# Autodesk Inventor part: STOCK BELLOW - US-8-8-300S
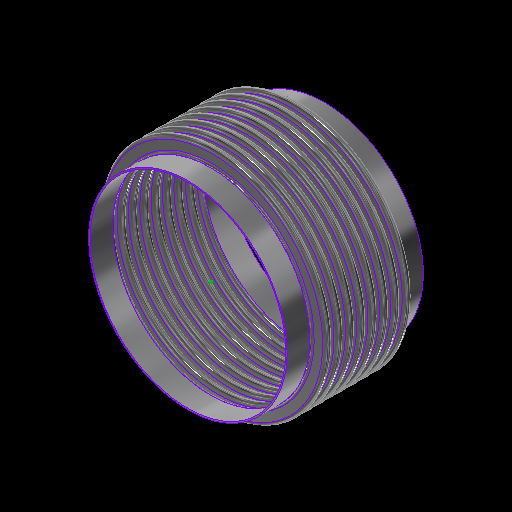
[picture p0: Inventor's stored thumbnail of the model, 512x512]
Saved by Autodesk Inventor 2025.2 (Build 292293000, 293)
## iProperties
Category: 22 GA (0.030 THICK)
RuleStatus: InUse
Created: 2024-01
Part Number: STOCK BELLOW - US-8-8-300S
Project: =STOCK BELLOWS: <Stock Number><SFILL>
Material: ASTM A240-304
Description: =STOCK BELLOWS: <Stock Number>, <SID_> I.D., <SOD_> O.D., <SPLY_> PLY, <Category>, <SNET_CONS> CONS.<PITCH_><STANGENT_> TANGENT<SFILL>
Document SubType Name: Sheet Metal
Designer: GS
Stock Number: U.S-8-8-300S
Surface Area: 5419.46 cm^2
Volume: 408.134 cm^3
Sheet Metal Rule: Default
Appearance: STAINLESS STEEL
Mass: 3288.45 g
Density: 8.05729 g/cm^3
THK: 0.036
ID: 3.500
OD: 4.250
CONS_: 2
PITCH: 0.500
TANGENT: 0.500
BELLOWS_UPSET: 0.000
d79: 1.000
d82: 1.000
d83: 26.000
d84: 24.000
d174: 8
d214: 8
STHK_: 0.030
SID_: 8.625
SOD_: 10.000
SPITCH_: 0.500
STANGENT__: 1.000
SBELLOWS_UPSET_: 0.000
SDIFF_TAN: 1.000
d252: 2
d275: 2
d287: 0.050
d289: 0.500
d290: 0.000
SOD_NECK: 8 3/4
PLY: 1
PSET: 4.178
PBAR: 1.035
COUNTER: 1.500
NET_TUBE: 3.071
CONS: 2
S_CONS: 0
NET_CONS: 2
ID_M: 88.90 mm
OD_M: 107.95 mm
THK_M: 0.91 mm
ID_U: 3.500 in
OD_U: 4.250 in
THK_U: 0.036 in
TANGENT2: 0.500
TAN_TO_TAN: 1.000 in
d80: 2.571
d81: 10
SID: 2.375
SCONS_: 8
SPITCH: 0.250
STANGENT_: 1.000
SBELLOWS_UPSET: 0.000
SNET_CONS: 8
SS_CONS: 0
SCONS: 8
d190: 8
d191: 1
d192: 1
d193: 8
d194: 0
SIZE: 8.00
PRESSURE: 300
d230: 8
STANGENT: 4.000
SPLY_: 2
d233: 8
d234: 0
d263: 2
d265: 1
d268: 2
d269: 0
d286: 2
d288: 1
d291: 2
d292: 0
SREROLL: 0.750
BLETP: 0.000 ul
PRES_Copy: 85
MATTABLE: 20 GA (0.036 THICK)
PART_NUMBER: U.S-8-8-300S
PITCH_: =, <SPITCH_> PITCH,
CFILL: .
SFILL: .
MESH: ,
COMP: 0.82
EXT: 0.41
LAT: 0.11
ANG: 573
ASR: 3697
LSR: 30059
ANSR: 700
PRES: 300
COMPM: 8.2
EXTM: 4.1
LATM: 1.10
ASRM: 647.456
PRESM: 20.684
LSRM: 5264.233
ANSRM: 122.591
TEMPMIN: 20
TEMPMAX: 800
TEMPMINM: -7
TEMPMAXM: 427
WEIGHTM: 3.288
WEIGHT: 7.250
Author: GS
Keywords: 20 GA (0.036 THICK)
Comments: =STOCK BELLOW - <STOCK NUMBER>
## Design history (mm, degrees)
sketch "Sketch2"
  geometry: L1 (0, -177.245)-(0, 562.856) reference; L2 (45.364, 0)-(44.45, 0); L3 (48.082, -2.718)-(50.343, -2.718); L4 (48.082, -3.632)-(50.343, -3.632); L5 (50.343, -9.982)-(48.082, -9.982); L6 (50.343, -9.068)-(48.082, -9.068); L7 (45.364, -12.7)-(44.45, -12.7); L8 (48.082, 0)-(48.082, -12.7); L9 (50.343, -6.35)-(53.975, -6.35); L10 (44.45, 0)-(44.45, -12.7); L11 (20.376, 102.841)-(20.376, 101.926); L12 (58.262, 457.127)-(58.262, 349.177); L13 (58.262, 444.427)-(58.262, 336.477); L14 (93.133, -58.817)-(93.133, -71.517); L15 (118.746, -66.401)-(118.746, -66.401); L16 (50.343, -9.068)-(50.343, -9.982); L17 (48.082, -9.068)-(48.082, -9.982); L18 (48.082, -9.525)-(50.343, -9.525); L19 (53.975, 0)-(53.975, -12.7); L20 (-50.343, -9.068)-(-50.343, -9.982); L21 (-50.343, -2.718)-(-48.082, -2.718); L22 (-50.343, -3.632)-(-48.082, -3.632); L23 (-48.082, -9.068)-(-50.343, -9.068); L24 (-50.343, -9.525)-(-48.082, -9.525); L25 (-48.082, -9.982)-(-50.343, -9.982); L26 (-48.082, -9.068)-(-48.082, -9.982); L27 (-44.45, 0.653)-(-44.45, -12.047); L28 (-48.082, -6.35)-(-44.45, -6.35); L29 (-50.343, 0.653)-(-50.343, -12.7); L30 (-53.061, 0)-(-53.975, 0); L31 (-53.975, 0)-(-53.975, -12.7); L32 (-53.061, -12.7)-(-53.975, -12.7); A1 r 2.718 centre (48.082, 0) between (45.364, 0) and (48.082, -2.718); A2 r 3.632 centre (48.082, 0) between (44.45, 0) and (48.082, -3.632); A3 r 3.632 centre (50.343, -6.35) between (50.343, -9.982) and (50.343, -2.718); A4 r 2.718 centre (50.343, -6.35) between (50.343, -9.068) and (50.343, -3.632); A5 r 2.718 centre (48.082, -12.7) between (48.082, -9.982) and (45.364, -12.7); A6 r 3.632 centre (48.082, -12.7) between (48.082, -9.068) and (44.45, -12.7); A7 r 3.175 centre (50.343, -6.35) between (50.343, -9.525) and (53.518, -6.35); A8 r 3.175 centre (48.082, -12.7) between (48.082, -9.525) and (44.907, -12.7); A9 r 2.718 centre (-50.343, -12.7) between (-50.343, -9.982) and (-53.061, -12.7); A10 r 2.718 centre (-48.082, -6.35) between (-48.082, -9.068) and (-48.082, -3.632); A11 r 3.175 centre (-48.082, -6.35) between (-48.082, -9.525) and (-44.907, -6.35); A12 r 3.632 centre (-48.082, -6.35) between (-48.082, -9.982) and (-48.082, -2.718); A13 r 3.175 centre (-50.343, -12.7) between (-50.343, -9.525) and (-53.518, -12.7); A14 r 3.632 centre (-50.343, -12.7) between (-50.343, -9.068) and (-53.975, -12.7); A15 r 2.718 centre (-50.343, 0) between (-53.061, 0) and (-50.343, -2.718); A16 r 3.632 centre (-50.343, 0) between (-53.975, 0) and (-50.343, -3.632); 10 further points
  constraints: 62 end point, 38 point on circle, 20 tangent, 16 centre point, 12 parallel, 9 midpoint, 7 vertical, 6 coincident, 6 concentric, 6 point on line, 4 equal radius, 4 perpendicular, 3 horizontal, 1 collinear, 1 horizontal alignment, 10 other
  dimensions: "THK" = 0.9144 distance of L11.start L11.end; "ID" = 88.9 distance of L11.end point (20.376, 13.026); "OD" = 107.95 distance of L12.start L12.end; "PITCH" = 12.7 distance of L12.start L13.start; "TANGENT" = 12.7 distance of L14.start L14.end; "BELLOWS_UPSET" = 0 distance of L15.start L15.end; "d43" = 88.9 diameter of L10 L1 (= ID); "d44" = 107.95 diameter of L9.end L1 (= OD); "d45" = 0.9144 distance between parallel lines of L5 L6 (computed from THK, PLY); "d46" = 3.6322 radius of A3 (computed from PITCH, THK, PLY); "UPSET_PITCH" = 12.7 distance of L2.end L7.end (derived); "SIDEWALL_ANGLE" = 360 deg dimension on L3 L9 (derived); "CON_GAP" = 5.4356 distance of point (48.082, -9.068) point (48.082, -3.632) (derived); "TAN1" = 4.98728 dimension on A8 (derived); "TAN2" = 4.98728 dimension on A7 (derived); "LEG1" = 2.2606 distance of L18.start L18.end (derived); "d278" = 0.9144 distance between parallel lines of L25 L23 (derived); "d279" = 3.6322 radius of A12 (derived); "d280" = 12.7 distance of L30.end L31.end (derived); "d281" = 360 deg dimension on L21 L28 (derived); "d282" = 5.4356 distance of point (-50.343, -9.068) point (-50.343, -3.632) (derived); "d283" = 4.98728 dimension on A13 (derived); "d284" = 4.98728 dimension on A11 (derived); "d285" = 2.2606 distance of L24.start L24.end (derived); "d293" = 88.9 diameter of L27 L1 (derived); "d294" = 107.95 diameter of L31 L1 (derived)
  node "Sketch Rectangular Pattern1" dims "d31" = 25.4, "ID" = 88.9
  node "Sketch Rectangular Pattern2" dims "d39" = 25.4, "PITCH" = 12.7
revolve "CONS" stored, may be unused: angle "d48" = 90 deg
node "BELLOW MIDPLANE"
pattern_linear "Rectangular Pattern2" dims "d52" = 12.7 (= UPSET_PITCH)
sketch "Sketch5"
  geometry: C1 r 45.364 at (0, 0) reference; C2 r 44.45 at (0, 0) reference
extrude "TANGENT" new body sketch "Sketch5" distance "d53" = 12.7 (= TANGENT); taper "d54" = 0 deg
revolve "SAMETAN" stored, may be unused: angle "d65" = 90 deg
revolve "DIFFTAN" stored, may be unused: angle "d70" = 90 deg
sketch "Sketch9"
  geometry: L1 (53.319, 0)-(-53.319, 0) reference; L2 (0, -17.78)-(0, 17.78) reference; L3 (38.085, 0)-(-38.085, 0); L4 (38.085, -11.906)-(38.085, 11.906); L5 (25.385, -11.906)-(25.385, 11.906); L6 (13.15, 11.906)-(13.15, -11.906); L7 (-25.385, -11.906)-(-25.385, 11.906); L8 (-38.085, -11.906)-(-38.085, 11.906); L9 (37.291, -11.906)-(37.291, 11.906); L10 (38.085, -11.906)-(37.291, -11.906); L11 (38.085, 11.906)-(37.291, 11.906); L12 (13.546, 11.906)-(12.753, 11.906); L13 (12.753, 11.906)-(12.753, -11.906); L14 (12.753, -11.906)-(13.546, -11.906); L15 (13.546, -11.906)-(13.546, 11.906); L16 (-13.546, 11.906)-(-13.546, -11.906); L17 (-13.15, 11.906)-(-13.15, -11.906); L18 (-13.546, -11.906)-(-12.753, -11.906); L19 (-12.753, -11.906)-(-12.753, 11.906); L20 (-12.753, 11.906)-(-13.546, 11.906); L21 (-38.085, -11.906)-(-37.291, -11.906); L22 (-37.291, -11.906)-(-37.291, 11.906); L23 (-37.291, 11.906)-(-38.085, 11.906); L24 (-38.085, 11.906)-(-38.085, -11.906); L25 (38.085, -0.397)-(-38.085, -0.397); L26 (-38.085, -0.397)-(-38.085, 0.397); L27 (-38.085, 0.397)-(38.085, 0.397); L28 (38.085, 0.397)-(38.085, -0.397); L29 (-38.085, 11.906)-(38.085, 11.906); L30 (38.085, 11.906)-(38.085, 12.7); L31 (38.085, 12.7)-(-38.085, 12.7); L32 (-38.085, 12.7)-(-38.085, 11.906); L33 (38.085, -11.906)-(-38.085, -11.906); L34 (-38.085, -11.906)-(-38.085, -12.7); L35 (-38.085, -12.7)-(38.085, -12.7); L36 (38.085, -12.7)-(38.085, -11.906); 30 further points
  constraints: 68 end point, 13 midpoint, 13 parallel, 8 horizontal, 7 perpendicular, 6 equal length, 3 point on line, 2 vertical, 14 other
  dimensions: "d115" = 23.8125 distance of L4.start L4.end (derived); "d116" = 12.7 distance between parallel lines of L4 L5 (derived); "d117" = 12.23516 distance between parallel lines of L5 L6 (derived); "d125" = 38.53427 distance between parallel lines of L7 L6 (derived); "d127" = 12.7 distance between parallel lines of L8 L7 (derived); "d128" = 24.93516 distance between parallel lines of L6 L4 (derived); "d130" = 76.16943 distance between parallel lines of L8 L4 (derived); "RULER_THK" = 0.79375 distance between parallel lines of L4 L9; "d135" = 0.79375 distance of L13.end L14.end (derived); "d138" = 26.29911 distance of L13.end L16.end (derived); "d143" = 0.79375 distance of L22.end L8.end (derived); "d144" = 0.79375 distance between parallel lines of L27 L25 (derived)
extrude "RULER" join sketch "Sketch9" distance "d149" = 0.79375 (derived); taper "d150" = 0 deg
extrude "BARS" join sketch "Sketch9" distance "d151" = 0.79375 (derived); taper "d152" = 0 deg
pattern_linear "Rectangular Pattern4" dims "d155" = 26.29911 (derived)
sketch "Sketch13"
  geometry: L1 (93.149, -52.467)-(93.149, -77.867); L2 (111.061, 0)-(109.537, 0); L3 (111.061, -12.7)-(109.537, -12.7); L4 (123.063, -10.287)-(113.475, -10.287); L5 (123.063, -8.763)-(113.475, -8.763); L6 (123.063, -6.35)-(127, -6.35); L7 (113.475, -2.413)-(123.063, -2.413); L8 (113.475, 0)-(113.475, -12.7); L9 (109.537, 0)-(109.537, -12.7); L10 (58.254, -242.431)-(58.254, -496.431); L11 (58.254, -255.131)-(58.254, -509.131); L12 (58.254, -280.531)-(58.254, -534.531); L13 (58.254, -293.231)-(58.254, -547.231); L14 (58.254, -305.931)-(58.254, -559.931); L15 (58.254, -318.631)-(58.254, -572.631); L16 (58.254, -331.331)-(58.254, -585.331); L17 (58.254, -267.831)-(58.254, -521.831); L18 (20.376, 102.688)-(20.376, 101.926); L19 (113.475, -3.937)-(123.063, -3.937); L20 (0, -722.935)-(0, 240.292) reference; L21 (-25.4, 0)-(152.4, 0) reference; A1 r 2.413 centre (113.475, 0) between (111.061, 0) and (113.475, -2.413); A2 r 2.413 centre (113.475, -12.7) between (113.475, -10.287) and (111.061, -12.7); A3 r 3.937 centre (113.475, -12.7) between (113.475, -8.763) and (109.537, -12.7); A4 r 2.413 centre (123.063, -6.35) between (123.063, -8.763) and (123.063, -3.937); A5 r 3.937 centre (123.063, -6.35) between (123.063, -10.287) and (123.063, -2.413); A6 r 3.937 centre (113.475, 0) between (109.537, 0) and (113.475, -3.937); 6 further points; 1 other entity
  constraints: 38 end point, 15 point on circle, 9 tangent, 6 centre point, 6 parallel, 5 vertical alignment, 4 point on line, 4 vertical, 3 coincident, 3 concentric, 2 collinear, 2 equal radius, 1 horizontal, 1 perpendicular, 23 other
  dimensions: "SBELLOWS_UPSET_" = 0 distance of point (118.762, -66.401) point (118.762, -66.401); "STOTAL_THK_BELLOW__" = 1.524 distance between parallel lines of L4 L5 (derived); "d224" = 3.937 radius of A5 (derived); "d225" = 12.7 distance of L2.end L3.end (derived); "SSIDEWALL_ANGLE_" = 360 deg dimension on L7 L6 (derived); "SSCON_GAP_" = 4.826 distance of point (113.474, -8.763) point (113.475, -3.937) (derived); "d235" = 219.075 diameter of L9 L20 (derived); "d236" = 254 diameter of L6.end L20 (derived)
  node "Sketch Rectangular Pattern4" dims "d228" = 25.4
  node "Sketch Rectangular Pattern5" dims "d229" = 25.4
revolve "SBELLOW" stored, may be unused: angle "d197" = 90 deg
pattern_linear "Rectangular Pattern5" dims "d204" = 12.7 (derived)
revolve "STANGENT" stored, may be unused: angle "d240" = 90 deg
revolve "SSAMETAN" stored, may be unused: angle "d241" = 90 deg
revolve "SDIFFTAN" stored, may be unused: angle "d246" = 90 deg
revolve "INVCON" stored, may be unused: angle "d295" = 90 deg
pattern_linear "Rectangular Pattern6" dims "d298" = 12.7 (derived)
revolve "INVTANGENT" stored, may be unused: angle "d302" = 90 deg
revolve "INVSAMETAN" stored, may be unused: angle "d307" = 90 deg
revolve "INVDIFFTAN" stored, may be unused: angle "d312" = 90 deg
sketch "ID BELLOW MOUNT CALC"
  geometry: L1 (44.45, 0)-(38.1, 0); L2 (38.1, 0)-(38.1, 12.7); L3 (38.1, 12.7)-(44.45, 12.7); L4 (44.45, 12.7)-(44.45, 0); L5 (36.513, 12.7)-(35.598, 12.7); L6 (35.598, 12.7)-(35.598, 0); L7 (35.598, 0)-(36.513, 0); L8 (36.513, 0)-(36.513, 12.7); L9 (0, -2.54)-(0, 15.24) reference; L10 (-8.89, 0)-(53.34, 0) reference; 1 further point
  constraints: 16 end point, 5 parallel, 2 collinear, 2 horizontal, 2 perpendicular
  dimensions: "d314" = 12.7 distance of L5.end L6.end (derived); "d315" = 0.9144 distance of L5.start L5.end (derived); "IG" = 1.5875 distance between parallel lines of L2 L8; "PIPE_OD" = 88.9 diameter of L4 L9; "PIPE_WALL" = 6.35 distance of L2.end L3.end; "ID_MT_BELLOW" = 71.1962 diameter of L6 L9 (derived)
revolve "CFILL" stored, may be unused: angle "d320" = 90 deg
pattern_linear "Rectangular Pattern7" dims "d323" = 12.7 (derived)
revolve "SFILL" stored, may be unused: angle "d324" = 90 deg
pattern_linear "Rectangular Pattern8" dims "d327" = 12.7 (derived)
node "STOCK BELLOW MIDPLANE"
node "BELLOW"
sketch "Sketch6"
  geometry: L1 (-12.7, 45.364)-(0, 45.364); L2 (0, 45.364)-(0, 44.45); L3 (0, 44.45)-(-12.7, 44.45); L4 (-12.7, 44.45)-(-12.7, 45.364); L5 (10.16, 0)-(-60.96, 0) reference; L6 (-38.1, -89.422)-(-38.1, 153.44) reference; 1 further point
  constraints: 8 end point, 2 parallel, 1 horizontal, 1 perpendicular
  dimensions: "d61" = 12.7 distance of L2.end L3.end (derived); "d62" = 0.9144 distance of L1.end L2.end (derived); "d63" = 88.9 diameter of L3 L5 (derived); "d64" = 25.4 distance between parallel lines of L4 L6 (derived)
sketch "Sketch12"
  geometry: 1 further point
sketch "Sketch14"
  geometry: L1 (-25.4, 111.061)-(0, 111.061); L2 (0, 111.061)-(0, 109.537); L3 (0, 109.537)-(-25.4, 109.537); L4 (-25.4, 109.537)-(-25.4, 111.061); L5 (5.08, 0)-(-30.48, 0) reference; L6 (0, -22.212)-(0, 133.274) reference; 1 further point
  constraints: 8 end point, 2 parallel, 1 collinear, 1 horizontal, 1 perpendicular
  dimensions: "d237" = 1.524 distance of L3.end L1.start (derived); "d238" = 219.075 diameter of L3 L5 (derived); "d239" = 25.4 distance of L1.start L1.end (derived); "SOD_NECK" = 222.123 diameter of L1 L5 (derived)
sketch "Sketch15"
  geometry: L1 (-22.212, 0)-(133.274, 0) reference; L2 (109.538, -101.6)-(111.062, -101.6); L3 (111.062, -101.6)-(111.062, -127); L4 (111.062, -127)-(109.537, -127); L5 (109.537, -127)-(109.538, -101.6); L6 (0, -154.94)-(0, 40.64) reference; 1 further point
  constraints: 8 end point, 2 parallel, 1 horizontal, 1 perpendicular
  dimensions: "d205" = 25.4 distance of L4.end L2.start (derived); "d206" = 1.524 distance of L3.end L4.end (derived); "d207" = 219.075 diameter of L5 L6 (derived); "d208" = 101.6 distance between parallel lines of L1 L2 (derived)
node "TANGENT_"
node "SAME_TAN"
sketch "Sketch8"
  geometry: L1 (45.364, -25.4)-(44.45, -25.4); L2 (44.45, -25.4)-(44.45, -38.1); L3 (44.45, -38.1)-(45.364, -38.1); L4 (45.364, -38.1)-(45.364, -25.4); L5 (0, -48.26)-(0, 22.86) reference; L6 (-89.422, 0)-(153.44, 0) reference; 1 further point
  constraints: 8 end point, 2 parallel, 1 horizontal, 1 perpendicular
  dimensions: "d66" = 88.9 diameter of L2 L5 (derived); "TOTAL_THK_BELLOW" = 0.9144 distance of L2.end L3.end (derived); "d68" = 25.4 distance between parallel lines of L1 L6 (derived); "d69" = 12.7 distance of L1.end L2.end (derived)
node "DIFF_TAN"
node "Sketch Rectangular Pattern3" dims "d138" = 26.29911 (derived), "d141" = 25.4
node "SBELLOW_"
node "STANGENT_"
node "SSAME_TAN"
sketch "Sketch16"
  geometry: L1 (111.061, -101.6)-(109.538, -101.6); L2 (109.538, -101.6)-(109.538, -127); L3 (109.538, -127)-(111.062, -127); L4 (111.062, -127)-(111.061, -101.6); L5 (0, -154.94)-(0, 40.64) reference; L6 (-22.212, 0)-(133.274, 0) reference; 1 further point
  constraints: 8 end point, 2 parallel, 1 horizontal, 1 perpendicular
  dimensions: "SDIFF_TAN" = 25.4 distance of L3.end L1.start; "d243" = 1.524 distance of L2.end L3.end (derived); "d244" = 101.6 distance between parallel lines of L1 L6 (derived); "d245" = 219.075 diameter of L2 L5 (derived)
node "SDIFF_TAN"
body "Solid15"
sketch "Sketch17"
  geometry: L1 (53.975, 12.7)-(53.061, 12.7); L2 (53.061, 12.7)-(53.061, 0); L3 (53.061, 0)-(53.975, 0); L4 (53.975, 0)-(53.975, 12.7); L5 (0, -2.54)-(0, 15.24) reference; L6 (-10.795, 0)-(64.77, 0) reference; 2 further points
  constraints: 8 end point, 2 parallel, 1 horizontal, 1 midpoint, 1 perpendicular, 1 point on line
  dimensions: "INVTANGENT" = 12.7 distance of L3.end L1.start (derived); "d300" = 0.9144 distance of L1.start L1.end (derived); "d301" = 107.95 diameter of L4 L5 (derived)
body "Solid16"
sketch "Sketch18"
  geometry: L1 (53.975, -25.4)-(53.061, -25.4); L2 (53.061, -25.4)-(53.061, -38.1); L3 (53.061, -38.1)-(53.975, -38.1); L4 (53.975, -38.1)-(53.975, -25.4); L5 (-10.795, 0)-(64.77, 0) reference; L6 (0, -48.26)-(0, 22.86) reference; 1 further point
  constraints: 8 end point, 2 parallel, 1 horizontal, 1 perpendicular
  dimensions: "d303" = 25.4 distance between parallel lines of L1 L5 (derived); "d304" = 12.7 distance of L3.end L1.start (derived); "d305" = 0.9144 distance of L2.end L3.end (derived); "d306" = 107.95 diameter of L4 L6 (derived)
body "Solid17"
sketch "Sketch19"
  geometry: L1 (53.975, -25.4)-(53.061, -25.4); L2 (53.061, -25.4)-(53.061, -38.1); L3 (53.061, -38.1)-(53.975, -38.1); L4 (53.975, -38.1)-(53.975, -25.4); L5 (0, -48.26)-(0, 22.86) reference; L6 (-10.795, 0)-(64.77, 0) reference; 1 further point
  constraints: 8 end point, 2 parallel, 1 horizontal, 1 perpendicular
  dimensions: "d308" = 12.7 distance of L1.end L2.end (derived); "d309" = 107.95 diameter of L4 L5 (derived); "d310" = 0.9144 distance of L2.end L3.end (derived); "d311" = 25.4 distance between parallel lines of L1 L6 (derived)
body "Solid18"
body "Solid19"
body "Solid20"
other parameters: "BMPL" = -50.8, "PSET" = 106.1212 (computed from OD, THK, PLY) [user parameter], "PBAR" = 26.29911 (= 0.570796 x PITCH + OD - ID) [user parameter; used in 1 equation term], "COUNTER" = 15 [user parameter], "NET_TUBE" = 77.99823 (computed from CONS_, PBAR, TANGENT) [user parameter], "S_CONS" = 0 [user parameter; used in 1 equation term], "ID_M" = 88.9 (= ID) [user parameter], "OD_M" = 107.95 (= OD) [user parameter], "THK_M" = 0.9144 (= THK) [user parameter], "ID_U" = 88.9 (= ID) [user parameter], "OD_U" = 107.95 (= OD) [user parameter], "THK_U" = 0.9144 (= THK) [user parameter], "D_UNITS" = 0 [user parameter], "TANGENT2" = 12.7 [user parameter], "TAN_TO_TAN" = 25.4 [user parameter], "OD_NECK" = 90.7288 [user parameter], "d79" = 25.4, "d80" = 65.29823 [user parameter], "d82" = 25.4, "d83" = 660.4, "d84" = 609.6, "sa_0" = 4, "FRAME_THK" = 0.79375 [user parameter], "CON_FLAT" = 12.23516 [user parameter], "SID" = 60.325 [user parameter], "SPITCH" = 6.35 [user parameter], "STANGENT_" = 25.4 [user parameter], "SBELLOWS_UPSET" = 0 [user parameter], "SS_CONS" = 0 [user parameter], "STAN_TO_TAN_" = 101.6 [user parameter], "d100" = 1.524 [user parameter], "d191" = 25.4 [user parameter], "d194" = 0 [user parameter], "STANGENT" = 101.6 [user parameter], "d234" = 0 [user parameter], "SUPSET_PITCH_" = 12.7 [user parameter], "d269" = 0 [user parameter], "d287" = 1.27, "d289" = 12.7, "d290" = 0, "d292" = 0 [user parameter], "Thickness" = 3.048 (derived), "KFactor" = 4.4, "BendRadius" = 3.048 (derived), "BendReliefWidth" = 3.048 (derived), "BendReliefDepth" = 1.524 (derived), "CornerReliefSize" = 12.192 (derived), "SeamGap" = 0.00508, "MinimumRemnant" = 6.096 (derived), "TransitionRadius" = 3.048 (derived), "JacobiRadiusSize" = 3.048 (derived), "GapSize" = 3.048 (derived), "SREROLL" = 19.05 [user parameter], "CUR_STK_PITCH" = 12.7 [user parameter], "d328" = -50.8 (derived), "ASR" = 36970 [user parameter], "LSR" = 300590 [user parameter], "BLETP" = 0 [user parameter], "ASRM" = 6474.5561 [user parameter], "PRESM" = 206.83949 [user parameter], "LSRM" = 52642.3267 [user parameter], "ANSRM" = 1225.91 [user parameter], "TEMPMIN" = 2664.83333 [user parameter], "TEMPMAX" = 6998.16667 [user parameter], "TEMPMINM" = 2664.83333 [user parameter], "TEMPMAXM" = 6998.16667 [user parameter], "WEIGHT" = 32.88451 [user parameter], "WEIGHTM" = 0.03288 [user parameter]
